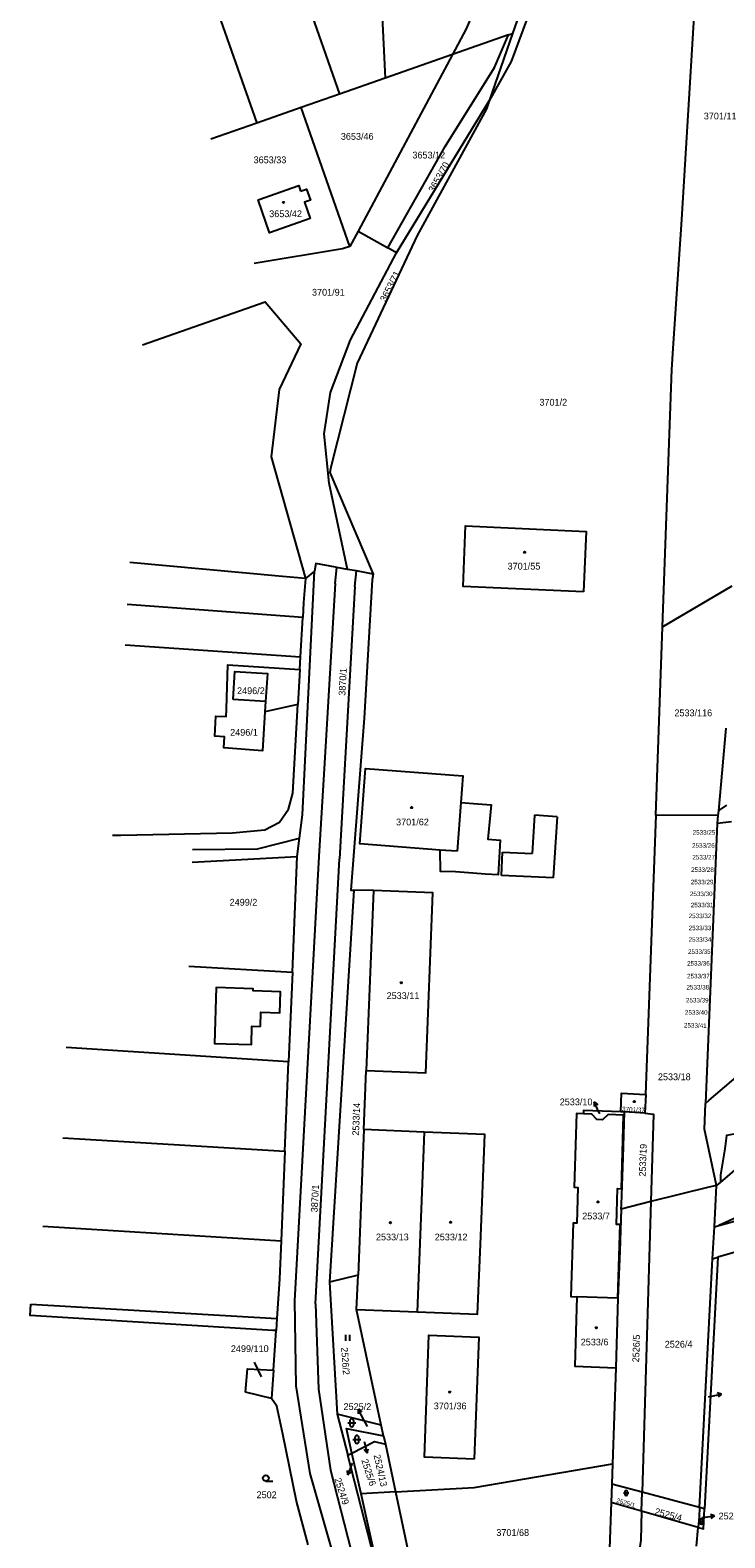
# Model space of a CAD drawing. Extents: x -527335 to -526256, y -1079142 to -1077809.
# Drawn here: x -527327.4 to -527153.1, y -1078442 to -1078063.8 of the extents above; entities that cross this region are included whole.
import ezdxf

# ---------------------------------------------------------------- set-up
doc = ezdxf.new("R2010")
doc.units = 0
for name, color, linetype in [('Vrstva 1', 7, 'Continuous'), ('Vrstva 2', 7, 'Continuous'), ('Vrstva 3', 7, 'Continuous'), ('Vrstva 4', 7, 'Continuous'), ('Vrstva 5', 7, 'Continuous'), ('Vrstva 7', 7, 'Continuous')]:
    doc.layers.add(name, color=color, linetype=linetype)

msp = doc.modelspace()

# ---------------------------------------------------------------- linework, layer by layer
at = {"layer": 'Vrstva 1'}
for p, q in [((-527265.02, -1078036.33), (-527249.76, -1078079.88)), ((-527240.25, -1078034.84), (-527238.34, -1078075.88)), ((-527287.85, -1078037.7), (-527270.53, -1078087.15)), ((-527207.36, -1078065.03), (-527221.44, -1078069.96)), ((-527206.41, -1078064.7), (-527212.24, -1078081.56)), ((-527207.36, -1078065.03), (-527206.41, -1078064.7)), ((-527221.44, -1078069.96), (-527245.09, -1078114.25)), ((-527221.44, -1078069.96), (-527238.34, -1078075.88)), ((-527238.34, -1078075.88), (-527249.76, -1078079.88)), ((-527249.76, -1078079.88), (-527259.42, -1078083.26)), ((-527235.46, -1078119.66), (-527212.24, -1078081.56)), ((-527259.42, -1078083.26), (-527270.53, -1078087.15)), ((-527247.2, -1078118.08), (-527259.42, -1078083.26)), ((-527270.53, -1078087.15), (-527282.07, -1078091.19)), ((-527245.09, -1078114.25), (-527247.2, -1078118.08)), ((-527245.09, -1078114.25), (-527237.62, -1078118.45)), ((-527235.46, -1078119.66), (-527237.62, -1078118.45)), ((-527256.05, -1078199.53), (-527258.33, -1078201.37)), ((-527168.74, -1078213.47), (-527151.32, -1078203.19)), ((-527258.98, -1078211.18), (-527302.99, -1078207.92)), ((-527259.53, -1078221), (-527258.98, -1078211.18)), ((-527170.45, -1078260.78), (-527168.74, -1078213.47)), ((-527303.57, -1078217.98), (-527259.53, -1078221)), ((-527259.71, -1078224.17), (-527259.53, -1078221)), ((-527259.71, -1078224.17), (-527260.22, -1078232.98)), ((-527170.45, -1078260.78), (-527172.99, -1078330.81)), ((-527154.85, -1078260.85), (-527170.45, -1078260.78)), ((-527155.03, -1078262.79), (-527157.99, -1078333.04)), ((-527154.85, -1078260.85), (-527155.03, -1078262.79)), ((-527155.03, -1078262.79), (-527151.46, -1078262.32)), ((-527286.76, -1078272.51), (-527260.37, -1078271.13)), ((-527261.59, -1078300.09), (-527260.37, -1078271.13)), ((-527246.22, -1078279.56), (-527252.26, -1078377.93)), ((-527241.23, -1078279.65), (-527246.22, -1078279.56)), ((-527241.23, -1078279.65), (-527243.05, -1078324.76)), ((-527287.55, -1078298.6), (-527261.59, -1078300.09)), ((-527261.59, -1078300.09), (-527262.54, -1078322.59)), ((-527262.54, -1078322.59), (-527318.37, -1078319)), ((-527263.48, -1078345.07), (-527262.54, -1078322.59)), ((-527243.66, -1078339.62), (-527243.05, -1078324.76)), ((-527178.25, -1078335.2), (-527179.24, -1078335.14)), ((-527173.19, -1078335.51), (-527178.25, -1078335.2)), ((-527319.16, -1078341.72), (-527263.48, -1078345.07)), ((-527243.66, -1078339.62), (-527245.13, -1078376.14)), ((-527228.5, -1078340.24), (-527243.66, -1078339.62)), ((-527228.5, -1078340.24), (-527230.33, -1078385.34)), ((-527263.48, -1078345.07), (-527264.43, -1078367.54)), ((-527155.75, -1078364.03), (-527155.2, -1078353.65)), ((-527154.21, -1078352.81), (-527155.2, -1078353.65)), ((-527171.66, -1078357.67), (-527179.09, -1078359.54)), ((-527171.66, -1078357.67), (-527173.85, -1078430.6)), ((-527324.19, -1078363.87), (-527264.43, -1078367.54)), ((-527156.18, -1078372.02), (-527155.75, -1078364.03)), ((-527155.75, -1078364.03), (-527154.6, -1078363.69)), ((-527154.86, -1078371.64), (-527158.24, -1078434.79)), ((-527156.18, -1078372.02), (-527154.86, -1078371.64)), ((-527245.13, -1078376.14), (-527252.26, -1078377.93)), ((-527245.48, -1078384.73), (-527245.13, -1078376.14)), ((-527252.26, -1078377.93), (-527250.32, -1078410.98)), ((-527327.19, -1078383.4), (-527265.48, -1078387.04)), ((-527179.93, -1078381.88), (-527190.26, -1078381.58)), ((-527179.93, -1078381.88), (-527180.46, -1078399.37)), ((-527265.48, -1078387.04), (-527265.68, -1078390.03)), ((-527239.29, -1078413.79), (-527245.48, -1078384.73)), ((-527245.48, -1078384.73), (-527230.33, -1078385.34)), ((-527266.33, -1078399.95), (-527265.68, -1078390.03)), ((-527180.46, -1078399.37), (-527181.31, -1078423.48)), ((-527266.33, -1078399.95), (-527266.79, -1078407.04)), ((-527266.79, -1078407.04), (-527273.35, -1078405.45)), ((-527239.29, -1078413.79), (-527250.32, -1078410.98)), ((-527250.32, -1078410.98), (-527247.66, -1078421.31)), ((-527238.72, -1078416.46), (-527239.29, -1078413.79)), ((-527238.72, -1078416.46), (-527238.27, -1078418.54)), ((-527238.27, -1078418.54), (-527235.72, -1078430.51)), ((-527247.66, -1078421.31), (-527246.64, -1078420.78)), ((-527239.04, -1078454.82), (-527247.66, -1078421.31)), ((-527244.36, -1078431), (-527246.64, -1078420.78)), ((-527181.31, -1078423.48), (-527181.49, -1078428.55)), ((-527181.49, -1078428.55), (-527181.65, -1078433.18)), ((-527173.85, -1078430.6), (-527181.49, -1078428.55)), ((-527235.72, -1078430.51), (-527244.36, -1078431)), ((-527239.04, -1078454.82), (-527244.36, -1078431)), ((-527235.72, -1078430.51), (-527229.87, -1078457.96)), ((-527181.65, -1078433.18), (-527182.05, -1078444.72)), ((-527173.99, -1078435.36), (-527181.65, -1078433.18)), ((-527173.99, -1078435.36), (-527173.85, -1078430.6)), ((-527159.44, -1078434.46), (-527173.85, -1078430.6)), ((-527159.81, -1078439.41), (-527173.99, -1078435.36)), ((-527158.24, -1078434.79), (-527159.44, -1078434.46)), ((-527160.26, -1078444.15), (-527159.81, -1078439.41))]:
    msp.add_line(p, q, dxfattribs=at)
for points in [[(-527195.06, -1078031.68), (-527200.73, -1078055.36), (-527206.71, -1078071.69), (-527212.24, -1078081.56)], [(-527198.62, -1078031.28), (-527203.07, -1078055.03), (-527206.41, -1078064.7)], [(-527240.25, -1078034.84), (-527212.84, -1078033.2), (-527210.76, -1078035.57), (-527213.81, -1078051.42), (-527215.47, -1078057.62), (-527217.99, -1078063.51), (-527221.44, -1078069.96)], [(-527168.74, -1078213.47), (-527166.4, -1078148.92), (-527166.12, -1078143.69), (-527163.93, -1078111.36), (-527159.33, -1078035.65)], [(-527237.62, -1078118.45), (-527223.31, -1078092.99), (-527210.88, -1078073.22), (-527207.36, -1078065.03)], [(-527212.24, -1078081.56), (-527212.93, -1078083.57), (-527230.3, -1078115.32), (-527245.35, -1078147.39), (-527251.94, -1078173.41), (-527252.16, -1078174.82), (-527241.36, -1078200.26)], [(-527259.52, -1078104.18), (-527258.06, -1078103.68), (-527257.08, -1078106.5), (-527258.53, -1078107.01), (-527257.1, -1078111.09), (-527267.32, -1078114.66), (-527270.18, -1078106.38), (-527259.99, -1078102.83), (-527259.52, -1078104.18)], [(-527247.2, -1078118.08), (-527249.02, -1078118.69), (-527271.16, -1078122.34)], [(-527247.79, -1078199.08), (-527252.39, -1078177.49), (-527253.58, -1078165.1), (-527252.03, -1078154.75), (-527247.04, -1078141.51), (-527235.46, -1078119.66)], [(-527299.19, -1078142.76), (-527268.42, -1078131.98), (-527259.44, -1078142.54), (-527264.92, -1078153.96), (-527266.9, -1078170.85), (-527258.33, -1078201.37)], [(-527188.59, -1078204.75), (-527218.79, -1078203.39), (-527218.19, -1078188.16), (-527187.92, -1078189.6), (-527188.59, -1078204.75)], [(-527258.33, -1078201.37), (-527264.07, -1078200.86), (-527302.38, -1078197.39)], [(-527247.79, -1078199.08), (-527250.45, -1078198.59), (-527250.81, -1078198.52), (-527255.75, -1078197.61), (-527256.05, -1078199.53)], [(-527241.36, -1078200.26), (-527245.51, -1078199.49), (-527247.79, -1078199.08)], [(-527260.37, -1078271.13), (-527259.78, -1078266.54), (-527259.05, -1078260.66), (-527256.05, -1078199.53)], [(-527258.33, -1078201.37), (-527258.77, -1078207.4), (-527258.98, -1078211.18)], [(-527241.36, -1078200.26), (-527241.57, -1078201.73), (-527243.62, -1078236.43), (-527246.94, -1078279.52), (-527246.22, -1078279.56)], [(-527260.22, -1078232.98), (-527268.53, -1078234.86), (-527269.1, -1078244.6), (-527278.75, -1078243.87), (-527278.58, -1078241.09), (-527281.07, -1078240.94), (-527280.76, -1078235.88), (-527278.21, -1078236.03), (-527278.12, -1078234.36), (-527278.1, -1078234.04), (-527277.82, -1078223.04), (-527259.71, -1078224.17)], [(-527276.48, -1078231.72), (-527276.03, -1078224.73), (-527267.86, -1078225.24), (-527268.31, -1078232.24), (-527276.48, -1078231.72)], [(-527306.7, -1078265.8), (-527304.61, -1078265.76), (-527276.63, -1078265.17), (-527268.51, -1078264.41), (-527264.86, -1078262.49), (-527262.53, -1078259.22), (-527261.46, -1078255.23), (-527260.22, -1078232.98)], [(-527152.87, -1078238.94), (-527154.74, -1078259.62), (-527154.85, -1078260.85)], [(-527216.33, -1078275.26), (-527220.68, -1078274.98), (-527224.45, -1078274.9), (-527224.49, -1078269.5), (-527244.65, -1078267.95), (-527243.27, -1078249.06), (-527218.84, -1078250.84), (-527219.37, -1078257.57), (-527215.05, -1078257.91), (-527211.77, -1078258.12), (-527212.56, -1078266.78), (-527209.44, -1078267.03), (-527210.01, -1078275.72), (-527213.23, -1078275.53), (-527216.33, -1078275.26)], [(-527243.05, -1078324.76), (-527228.16, -1078325.36), (-527226.34, -1078280.25), (-527241.23, -1078279.65)], [(-527078.01, -1078279.88), (-527149.04, -1078340.4), (-527152.71, -1078341.14), (-527153.16, -1078344.42), (-527154.22, -1078350.96), (-527154.21, -1078352.81)], [(-527157.99, -1078333.04), (-527157.02, -1078332.22), (-527108.84, -1078291.17)], [(-527269.62, -1078313.79), (-527269.54, -1078310.17), (-527264.75, -1078310.35), (-527264.56, -1078305.03), (-527271.42, -1078304.8), (-527271.4, -1078304.34), (-527280.74, -1078304.01), (-527281.16, -1078318.04), (-527278.17, -1078318.1), (-527271.88, -1078318.24), (-527271.72, -1078313.7), (-527269.62, -1078313.79)], [(-527179.24, -1078335.14), (-527179.02, -1078330.46), (-527172.99, -1078330.81)], [(-527172.99, -1078330.81), (-527172.9, -1078330.82), (-527173.19, -1078335.51)], [(-527128.03, -1078330.45), (-527128.68, -1078331), (-527154.21, -1078352.81)], [(-527179.24, -1078335.14), (-527188.58, -1078334.79), (-527188.61, -1078335.67)], [(-527179.09, -1078359.54), (-527179.05, -1078358.4), (-527178.64, -1078346.71), (-527178.25, -1078335.2)], [(-527173.19, -1078335.51), (-527171, -1078335.74), (-527171.66, -1078357.67)], [(-527155.2, -1078353.65), (-527158.26, -1078339.51), (-527157.99, -1078333.04)], [(-527188.61, -1078335.67), (-527190.37, -1078335.62), (-527190.95, -1078354.1), (-527189.98, -1078354.14), (-527190.25, -1078363.1), (-527191.19, -1078363.08), (-527191.76, -1078381.5), (-527190.26, -1078381.58)], [(-527179.93, -1078381.88), (-527179.39, -1078363.42), (-527180.32, -1078363.39), (-527180.05, -1078354.42), (-527179.08, -1078354.45), (-527178.53, -1078335.96), (-527182.41, -1078335.83), (-527183.78, -1078337.14), (-527185.21, -1078337.08), (-527186.5, -1078335.73), (-527188.61, -1078335.67)], [(-527230.33, -1078385.34), (-527215.14, -1078385.96), (-527214.42, -1078368.42), (-527213.28, -1078340.85), (-527228.5, -1078340.24)], [(-527115.65, -1078345.65), (-527152.02, -1078362.49), (-527154.6, -1078363.69)], [(-527155.2, -1078353.65), (-527157.18, -1078354.03), (-527171.66, -1078357.67)], [(-527154.6, -1078363.69), (-527151.91, -1078362.89), (-527124.8, -1078354.88)], [(-527179.09, -1078359.54), (-527179.47, -1078370.14), (-527179.93, -1078381.88)], [(-527068.7, -1078368.72), (-527110.78, -1078358.92), (-527154.86, -1078371.64)], [(-527264.43, -1078367.54), (-527264.83, -1078377.02), (-527265.48, -1078387.04)], [(-527159.44, -1078434.46), (-527157.97, -1078405.69), (-527156.18, -1078372.02)], [(-527265.68, -1078390.03), (-527266.52, -1078389.98), (-527327.36, -1078386.29), (-527327.19, -1078383.4)], [(-527190.26, -1078381.58), (-527190.79, -1078398.98), (-527180.46, -1078399.37)], [(-527216, -1078422.31), (-527228.49, -1078421.77), (-527227.33, -1078391.19), (-527214.83, -1078391.69), (-527216, -1078422.31)], [(-527273.35, -1078405.45), (-527272.86, -1078399.62), (-527266.33, -1078399.95)], [(-527257.62, -1078443.82), (-527260.56, -1078432.84), (-527263.99, -1078416.01), (-527265.53, -1078409.01), (-527266.79, -1078407.04)], [(-527246.64, -1078420.78), (-527248.02, -1078414.58), (-527238.72, -1078416.46)], [(-527246.64, -1078420.78), (-527240.99, -1078417.84), (-527238.27, -1078418.54)], [(-527235.72, -1078430.51), (-527215.99, -1078429.39), (-527181.31, -1078423.48)], [(-527173.99, -1078435.36), (-527174.21, -1078442.61), (-527179.21, -1078475.16)], [(-527159.44, -1078434.46), (-527159.56, -1078436.75), (-527159.81, -1078439.41)], [(-527159.81, -1078439.41), (-527158.51, -1078439.78), (-527158.24, -1078434.79)]]:
    msp.add_lwpolyline(points, dxfattribs=at)
at = {"layer": 'Vrstva 3'}
for p, q in [((-527248.22, -1078392.63), (-527248.22, -1078391.13)), ((-527247.22, -1078392.63), (-527247.22, -1078391.13)), ((-527247.69, -1078413.17), (-527245.69, -1078413.17)), ((-527247.19, -1078412.67), (-527247.19, -1078413.67)), ((-527246.19, -1078413.67), (-527246.19, -1078412.67)), ((-527246.42, -1078417.35), (-527244.42, -1078417.35)), ((-527245.92, -1078416.85), (-527245.92, -1078417.85)), ((-527244.92, -1078417.85), (-527244.92, -1078416.85)), ((-527268.25, -1078427.83), (-527266.5, -1078427.83)), ((-527178.52, -1078430.77), (-527177.18, -1078430.77)), ((-527178.19, -1078430.44), (-527178.19, -1078431.11)), ((-527177.52, -1078431.11), (-527177.52, -1078430.44)), ((-527159.34, -1078437.6), (-527159.34, -1078438.28)), ((-527158.68, -1078438.28), (-527158.68, -1078437.6)), ((-527159.68, -1078437.94), (-527158.34, -1078437.94))]:
    msp.add_line(p, q, dxfattribs=at)
msp.add_circle((-527268.25, -1078427.08), 0.75, dxfattribs=at)
for centre, radius, start, end in [((-527246.69, -1078412.67), 0.5, 0, 180), ((-527246.69, -1078413.67), 0.5, 180, 359.9879), ((-527245.42, -1078416.85), 0.5, 0, 180), ((-527245.42, -1078417.85), 0.5, 180, 359.9879), ((-527177.85, -1078430.44), 0.335, 0, 180), ((-527177.85, -1078431.11), 0.335, 180, 359.9879), ((-527159.01, -1078437.61), 0.335, 0, 180), ((-527159.01, -1078438.28), 0.335, 180, 359.9879)]:
    msp.add_arc(centre, radius, start, end, dxfattribs=at)
at = {"layer": 'Vrstva 4'}
for p, q in [((-527250.88, -1078202.63), (-527250.45, -1078198.59)), ((-527250.88, -1078202.63), (-527253.55, -1078247.66)), ((-527245.89, -1078203.41), (-527245.51, -1078199.49)), ((-527245.89, -1078203.41), (-527249.77, -1078271.7)), ((-527268.31, -1078232.24), (-527268.53, -1078234.86)), ((-527253.55, -1078247.66), (-527254.98, -1078271.09)), ((-527219.37, -1078257.57), (-527220.3, -1078269.74)), ((-527154.74, -1078259.62), (-527152.61, -1078258.22)), ((-527200.83, -1078260.77), (-527201.44, -1078270.33)), ((-527195.21, -1078261.13), (-527200.83, -1078260.77)), ((-527195.21, -1078261.13), (-527196.19, -1078276.45)), ((-527270.3, -1078269.21), (-527259.78, -1078266.54)), ((-527286.67, -1078269.34), (-527270.3, -1078269.21)), ((-527254.98, -1078271.09), (-527261.09, -1078382.54)), ((-527220.3, -1078269.74), (-527224.49, -1078269.5)), ((-527209.13, -1078275.84), (-527208.86, -1078270.02)), ((-527208.86, -1078270.02), (-527201.44, -1078270.33)), ((-527255.79, -1078383.3), (-527249.77, -1078271.7)), ((-527196.19, -1078276.45), (-527209.13, -1078275.84)), ((-527261.09, -1078382.54), (-527260.74, -1078403.91)), ((-527255.79, -1078383.3), (-527255.07, -1078404.73)), ((-527260.74, -1078403.91), (-527257.19, -1078425.85)), ((-527255.07, -1078404.73), (-527252.03, -1078425.08)), ((-527257.19, -1078425.85), (-527251.49, -1078445.79)), ((-527252.03, -1078425.08), (-527246.83, -1078445.33))]:
    msp.add_line(p, q, dxfattribs=at)
at = {"layer": 'Vrstva 5'}
for centre in [(-527263.82, -1078107.05), (-527203.37, -1078194.78), (-527231.69, -1078258.83), (-527234.3, -1078302.78), (-527175.86, -1078332.6), (-527184.95, -1078357.77), (-527237, -1078362.97), (-527221.91, -1078362.87), (-527185.37, -1078389.32), (-527222.12, -1078405.46)]:
    msp.add_circle(centre, 0.175, dxfattribs=at)
at = {"layer": 'Vrstva 7'}
for p, q in [((-527185.86, -1078332.67), (-527185.91, -1078333.79)), ((-527184.64, -1078335.41), (-527185.86, -1078332.67)), ((-527185.86, -1078332.67), (-527185, -1078333.38)), ((-527184.51, -1078335.7), (-527184.64, -1078335.41)), ((-527269.35, -1078401.68), (-527271.07, -1078397.98)), ((-527157.21, -1078406.64), (-527156.89, -1078406.57)), ((-527156.89, -1078406.57), (-527153.95, -1078405.95)), ((-527153.95, -1078405.95), (-527155.04, -1078405.66)), ((-527153.95, -1078405.95), (-527154.83, -1078406.64)), ((-527243.69, -1078412.42), (-527245.1, -1078409.77)), ((-527245.1, -1078409.77), (-527244.19, -1078410.42)), ((-527245.1, -1078409.77), (-527245.07, -1078410.89)), ((-527242.78, -1078414.13), (-527243.69, -1078412.42)), ((-527243.55, -1078417.85), (-527242.82, -1078420.76)), ((-527242.82, -1078420.76), (-527243.55, -1078419.91)), ((-527242.82, -1078420.76), (-527242.58, -1078419.67)), ((-527247.67, -1078426.26), (-527247.79, -1078425.15)), ((-527246.64, -1078423.44), (-527247.67, -1078426.26)), ((-527247.67, -1078426.26), (-527246.85, -1078425.49)), ((-527246.6, -1078423.34), (-527246.64, -1078423.44)), ((-527158.88, -1078436.93), (-527158.68, -1078436.91)), ((-527158.68, -1078436.91), (-527155.7, -1078436.54)), ((-527155.7, -1078436.54), (-527156.76, -1078436.17)), ((-527155.7, -1078436.54), (-527156.63, -1078437.16))]:
    msp.add_line(p, q, dxfattribs=at)

# ---------------------------------------------------------------- texts
at = {"layer": 'Vrstva 2'}
for s, height, p in [('3701/11', 1.7, (-527158.41, -1078086.21)), ('3653/46', 1.7, (-527249.44, -1078091.32)), ('3653/33', 1.7, (-527271.32, -1078097.21)), ('3653/12', 1.7, (-527231.49, -1078096.01)), ('3653/42', 1.7, (-527267.4, -1078110.73)), ('3701/91', 1.7, (-527256.68, -1078130.42)), ('3701/2', 1.7, (-527199.63, -1078158.01)), ('3701/55', 1.7, (-527207.62, -1078199.14)), ('2496/2', 1.7, (-527275.47, -1078230.38)), ('2533/116', 1.7, (-527165.78, -1078235.93)), ('2496/1', 1.7, (-527277.2, -1078240.81)), ('3701/62', 1.7, (-527235.58, -1078263.31)), ('2533/25', 1.139, (-527161.19, -1078265.64)), ('2533/26', 1.139, (-527161.35, -1078268.91)), ('2533/27', 1.139, (-527161.27, -1078271.86)), ('2533/28', 1.139, (-527161.58, -1078274.98)), ('2533/29', 1.139, (-527161.66, -1078278.09)), ('2499/2', 1.7, (-527277.33, -1078283.44)), ('2533/30', 1.139, (-527161.89, -1078281.05)), ('2533/32', 1.139, (-527162.2, -1078286.58)), ('2533/31', 1.139, (-527161.66, -1078283.85)), ('2533/33', 1.139, (-527162.2, -1078289.61)), ('2533/34', 1.139, (-527162.2, -1078292.5)), ('2533/36', 1.139, (-527162.59, -1078298.49)), ('2533/35', 1.139, (-527162.36, -1078295.53)), ('2533/37', 1.139, (-527162.59, -1078301.68)), ('2533/11', 1.7, (-527237.96, -1078306.88)), ('2533/38', 1.139, (-527162.75, -1078304.48)), ('2533/39', 1.139, (-527162.88, -1078307.73)), ('2533/40', 1.139, (-527163.13, -1078310.8)), ('2533/18', 1.7, (-527169.91, -1078327.23)), ('2533/10', 1.7, (-527194.54, -1078333.52)), ('2533/7', 1.7, (-527188.9, -1078362.15)), ('2533/13', 1.7, (-527240.63, -1078367.41)), ('2533/12', 1.7, (-527225.88, -1078367.41)), ('2533/6', 1.7, (-527189.27, -1078393.76)), ('2499/110', 1.7, (-527277.02, -1078395.43)), ('2526/4', 1.7, (-527168.2, -1078394.31)), ('2525/2', 1.7, (-527248.76, -1078409.96)), ('3701/36', 1.7, (-527226.13, -1078409.79)), ('2502', 1.7, (-527270.58, -1078432.08)), ('2525/3', 1.7, (-527154.7, -1078437.41)), ('3701/68', 1.7, (-527210.44, -1078441.55))]:
    msp.add_text(s, height=height, dxfattribs=at).set_placement(p)
for s, height, rotation, p in [('3653/70', 1.7, 61, (-527226.1, -1078104.67)), ('3653/71', 1.7, 63, (-527238.2, -1078132.1)), ('3870/1', 1.7, 87, (-527248.31, -1078230.82)), ('2533/41', 1.14, 359, (-527163.38, -1078314.02)), ('2533/14', 1.7, 88, (-527244.88, -1078341.16)), ('3701/37', 1.14, 357, (-527178.91, -1078335.01)), ('2533/19', 1.7, 88, (-527172.99, -1078351.44)), ('3870/1', 1.7, 87, (-527255.28, -1078360.4)), ('2526/5', 1.7, 88, (-527174.63, -1078398.03)), ('2526/2', 1.7, 274, (-527249.37, -1078394.29)), ('2525/6', 1.7, 288, (-527244.32, -1078422.57)), ('2524/13', 1.7, 283, (-527241.25, -1078421.31)), ('2524/9', 1.7, 288, (-527251.08, -1078427.28)), ('2525/1', 1.14, 344, (-527180.42, -1078433.14)), ('2525/4', 1.7, 345, (-527170.85, -1078436.15))]:
    msp.add_text(s, height=height, rotation=rotation, dxfattribs=at).set_placement(p)

doc.saveas('drawing.dxf')
